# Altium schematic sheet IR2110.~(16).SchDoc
size A4
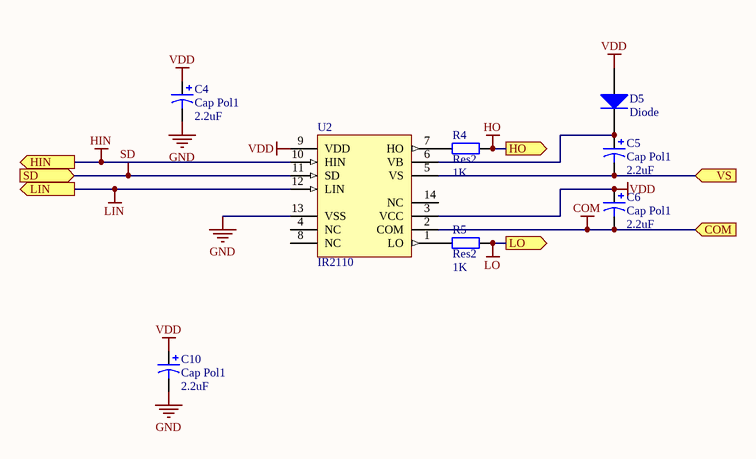
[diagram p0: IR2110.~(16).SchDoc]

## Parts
C4  Cap Pol1  value 2.2uF  [CAPPR2.5-6.3X5]
C5  Cap Pol1  value 2.2uF  [CAPPR2.5-6.3X5]
C6  Cap Pol1  value 2.2uF  [CAPPR2.5-6.3X5]
C10  Cap Pol1  value 2.2uF  [CAPPR2.5-6.3X5]
D5  Diode  [DO-204AL]
R4  Res2  value 1K  [AXIAL-0.4]
R5  Res2  value 1K  [AXIAL-0.4]
U2  IR2110  [PDIP14]

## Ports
COM (in), HIN (out), HO (out), LIN (out), LO (out), SD (in), VS (in)

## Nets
COM: C6.2 U2.2(COM) ; port COM
GND: C4.2 C10.2 U2.13(VSS)
HIN: U2.10(HIN) ; port HIN
HO: R4.2 ; port HO
LIN: U2.12(LIN) ; port LIN
LO: R5.2 ; port LO
SD: U2.11(SD) ; port SD
VDD: C4.1 C6.1 C10.1 D5.1(A) U2.3(VCC) U2.9(VDD)
VS: C5.2 U2.5(VS) ; port VS
NetC5_1: C5.1 D5.2(K) U2.6(VB)
NetR4_1: R4.1 U2.7(HO)
NetR5_1: R5.1 U2.1(LO)

Not connected (* = marked no-connect by the designer): U2 4(NC) 8(NC) 14(NC)

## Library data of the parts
C4-C6 C10 = Cap Pol1: Polarized Capacitor (Radial)
D5 = Diode: Default Diode
R4 R5 = Res2: Resistor
U2 = IR2110: High and Low Side Driver; Note: Pins 4, 8 and 14 are not connected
